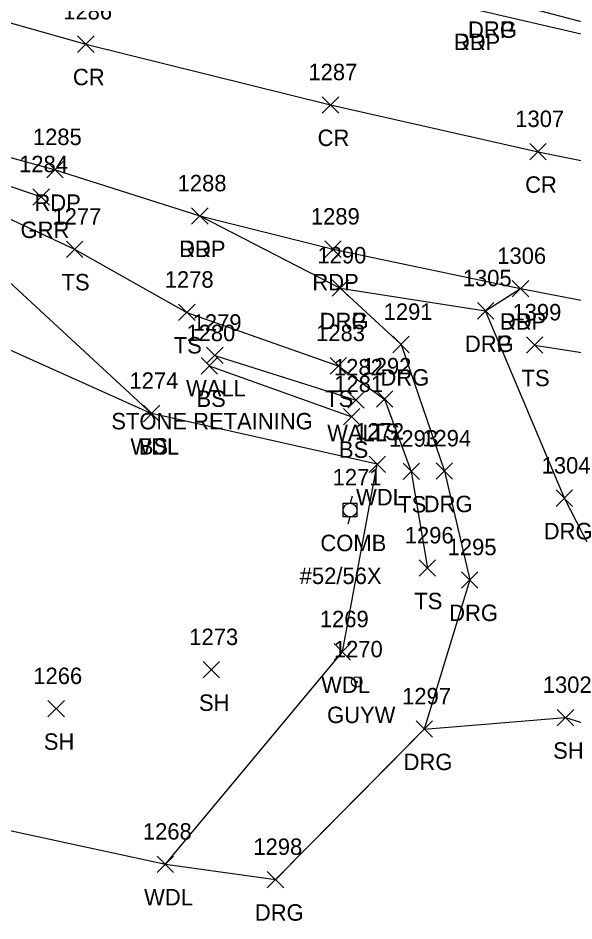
# Model space of a CAD drawing. Extents: x 1547013 to 1549434, y 267998 to 268739.
# Drawn here: x 1548599.8 to 1548667.4, y 267998.1 to 268107.9 of the extents above; entities that cross this region are included whole.
import ezdxf

# ---------------------------------------------------------------- set-up
doc = ezdxf.new("R2010")
doc.units = 0
for name, color, linetype in [('L_A', 7, 'Continuous'), ('L_C', 7, 'Continuous'), ('L_I', 7, 'Continuous'), ('L_TIC', 7, 'Continuous'), ('LAWA', 7, 'Continuous'), ('LELB', 7, 'Continuous'), ('LSOGP', 7, 'Continuous'), ('LW', 7, 'Continuous'), ('P_A', 7, 'Continuous'), ('P_I', 7, 'Continuous'), ('P_TIC', 7, 'Continuous'), ('PET', 7, 'Continuous'), ('PRC', 7, 'Continuous'), ('R_A', 7, 'Continuous'), ('R_I', 7, 'Continuous'), ('R_TIC', 7, 'Continuous'), ('RDG', 7, 'Continuous'), ('RDP', 7, 'Continuous'), ('RGR', 7, 'Continuous'), ('U_A', 7, 'Continuous'), ('U_C', 7, 'Continuous'), ('U_I', 7, 'Continuous'), ('UP', 7, 'Continuous'), ('UPGW', 7, 'Continuous')]:
    doc.layers.add(name, color=color, linetype=linetype)

msp = doc.modelspace()

# ---------------------------------------------------------------- linework, layer by layer
at = {"layer": 'L_TIC'}
for points in [[(1548605.66, 268078.82), (1548607.66, 268080.82)], [(1548607.66, 268078.82), (1548605.66, 268080.82)], [(1548619.32, 268071.15), (1548621.32, 268073.15)], [(1548621.32, 268071.15), (1548619.32, 268073.15)], [(1548661.66, 268067.17), (1548663.66, 268069.17)], [(1548663.66, 268067.17), (1548661.66, 268069.17)], [(1548622.73, 268065.92), (1548624.73, 268067.92)], [(1548624.73, 268065.92), (1548622.73, 268067.92)], [(1548622.05, 268064.65), (1548624.05, 268066.65)], [(1548624.05, 268064.65), (1548622.05, 268066.65)], [(1548637.75, 268064.65), (1548639.75, 268066.65)], [(1548639.75, 268064.65), (1548637.75, 268066.65)], [(1548643.4, 268060.61), (1548645.4, 268062.61)], [(1548645.4, 268060.61), (1548643.4, 268062.61)], [(1548639.92, 268060.48), (1548641.92, 268062.48)], [(1548641.92, 268060.48), (1548639.92, 268062.48)], [(1548615.03, 268058.85), (1548617.03, 268060.85)], [(1548617.03, 268058.85), (1548615.03, 268060.85)], [(1548615.03, 268058.85), (1548617.03, 268060.85)], [(1548617.03, 268058.85), (1548615.03, 268060.85)], [(1548639.4, 268058.46), (1548641.4, 268060.46)], [(1548641.4, 268058.46), (1548639.4, 268060.46)], [(1548642.5, 268052.68), (1548644.5, 268054.68)], [(1548644.5, 268052.68), (1548642.5, 268054.68)], [(1548646.64, 268051.81), (1548648.64, 268053.81)], [(1548648.64, 268051.81), (1548646.64, 268053.81)], [(1548648.6, 268040.05), (1548650.6, 268042.05)], [(1548650.6, 268040.05), (1548648.6, 268042.05)], [(1548638.26, 268029.86), (1548640.26, 268031.86)], [(1548640.26, 268029.86), (1548638.26, 268031.86)], [(1548622.31, 268027.69), (1548624.31, 268029.69)], [(1548624.31, 268027.69), (1548622.31, 268029.69)], [(1548603.42, 268022.95), (1548605.42, 268024.95)], [(1548605.42, 268022.95), (1548603.42, 268024.95)], [(1548665.42, 268021.87), (1548667.42, 268023.87)], [(1548667.42, 268021.87), (1548665.42, 268023.87)], [(1548616.71, 268004.03), (1548618.71, 268006.03)], [(1548618.71, 268004.03), (1548616.71, 268006.03)]]:
    msp.add_lwpolyline(points, dxfattribs=at)
at = {"layer": 'LAWA'}
msp.add_lwpolyline([(1548532.99, 268010.68), (1548542.3, 268026), (1548565.76, 268021.3), (1548592.57, 268010.46), (1548617.71, 268005.03), (1548639.26, 268030.86), (1548643.5, 268053.68), (1548616.03, 268059.85), (1548595.41, 268078.87)], dxfattribs=at)
at = {"layer": 'LELB'}
for points in [[(1548272.57, 268212.48), (1548289.14, 268210.26), (1548307.62, 268202.44), (1548323.1, 268196.35), (1548369.71, 268173.31), (1548388.46, 268161.7), (1548422.32, 268150.28), (1548459.33, 268134.33), (1548490.6, 268122.37), (1548528.34, 268109.13), (1548567.41, 268095.24), (1548592.2, 268086.56), (1548606.66, 268079.82), (1548620.32, 268072.15), (1548638.75, 268065.65), (1548644.4, 268061.61), (1548647.64, 268052.81), (1548649.6, 268041.05)], [(1548561.51, 268077.59), (1548574.57, 268080.17), (1548596.31, 268068.68), (1548616.03, 268059.85)], [(1548662.66, 268068.17), (1548718.89, 268059.45), (1548749.16, 268054.19), (1548786.26, 268048.98), (1548815.59, 268046.57), (1548864.84, 268043.79)], [(1548623.05, 268065.65), (1548640.4, 268059.46)]]:
    msp.add_lwpolyline(points, dxfattribs=at)
at = {"layer": 'LSOGP'}
msp.add_lwpolyline([(1548448.23, 268090.84), (1548475.05, 268075.85), (1548475.61, 268055.12), (1548494.63, 268042.02), (1548506.57, 268030.26), (1548514.3, 268026.68), (1548515.43, 268025.99), (1548520.54, 268019.12), (1548523.56, 268016.08), (1548532.99, 268010.68), (1548542.3, 268026), (1548565.76, 268021.3), (1548592.57, 268010.46), (1548617.71, 268005.03), (1548631.11, 268003.17), (1548635.64, 268007.75), (1548640.17, 268012.32), (1548644.7, 268016.9), (1548649.22, 268021.48), (1548666.42, 268022.87), (1548707.91, 268010.05)], dxfattribs=at)
at = {"layer": 'LW'}
msp.add_lwpolyline([(1548623.73, 268066.92), (1548640.92, 268061.48)], dxfattribs=at)
at = {"layer": 'P_TIC'}
for points in [[(1548607.02, 268103.77), (1548609.02, 268105.77)], [(1548609.02, 268103.77), (1548607.02, 268105.77)], [(1548636.81, 268096.38), (1548638.81, 268098.38)], [(1548638.81, 268096.38), (1548636.81, 268098.38)], [(1548662.07, 268090.69), (1548664.07, 268092.69)], [(1548664.07, 268090.69), (1548662.07, 268092.69)], [(1548603.28, 268088.49), (1548605.28, 268090.49)], [(1548605.28, 268088.49), (1548603.28, 268090.49)], [(1548620.9, 268082.87), (1548622.9, 268084.87)], [(1548622.9, 268082.87), (1548620.9, 268084.87)], [(1548637.12, 268078.83), (1548639.12, 268080.83)], [(1548639.12, 268078.83), (1548637.12, 268080.83)], [(1548659.94, 268074.04), (1548661.94, 268076.04)], [(1548661.94, 268074.04), (1548659.94, 268076.04)]]:
    msp.add_lwpolyline(points, dxfattribs=at)
at = {"layer": 'PET'}
for points in [[(1548291.29, 268251.79), (1548331.75, 268232.06), (1548365.57, 268215.99), (1548397.04, 268199.92), (1548430.53, 268185.01), (1548469.56, 268167.88), (1548505.57, 268153.53), (1548548.45, 268139.73), (1548572.84, 268130.65), (1548596.65, 268123.57), (1548616.57, 268118.19), (1548655.34, 268109.04), (1548680.93, 268103.12), (1548700.8, 268099.76), (1548753.55, 268092.31), (1548788.11, 268088.53), (1548842.08, 268084.26), (1548868.98, 268083.24)], [(1548277.31, 268222.58), (1548324.08, 268200.05), (1548370.89, 268177.56), (1548421.34, 268155.12), (1548457.66, 268139.55), (1548491.25, 268126.1), (1548528.96, 268112.02), (1548568.2, 268099.41), (1548604.28, 268089.49), (1548621.9, 268083.87), (1548638.12, 268079.83), (1548660.94, 268075.04), (1548683.04, 268070.81), (1548718.59, 268065.27), (1548750.02, 268060.75), (1548786.09, 268057.26), (1548818, 268054.36), (1548866.14, 268051.84)]]:
    msp.add_lwpolyline(points, dxfattribs=at)
at = {"layer": 'PRC'}
msp.add_lwpolyline([(1548285.23, 268237.15), (1548330.43, 268214.75), (1548376.37, 268192.58), (1548426.54, 268169.59), (1548464.29, 268153.5), (1548497.35, 268140.09), (1548534.69, 268126.49), (1548572.93, 268114.69), (1548608.02, 268104.77), (1548637.81, 268097.38), (1548663.07, 268091.69), (1548686.38, 268086.96), (1548723.69, 268081.05), (1548751.9, 268076.9), (1548786.74, 268073.36), (1548818.76, 268070.54), (1548866.8, 268068.08)], dxfattribs=at)
at = {"layer": 'R_TIC'}
for points in [[(1548601.59, 268085.19), (1548603.59, 268087.19)], [(1548603.59, 268085.19), (1548601.59, 268087.19)], [(1548620.9, 268082.87), (1548622.9, 268084.87)], [(1548622.9, 268082.87), (1548620.9, 268084.87)], [(1548638, 268074.1), (1548640, 268076.1)], [(1548640, 268074.1), (1548638, 268076.1)], [(1548638, 268074.1), (1548640, 268076.1)], [(1548640, 268074.1), (1548638, 268076.1)], [(1548659.94, 268074.04), (1548661.94, 268076.04)], [(1548661.94, 268074.04), (1548659.94, 268076.04)], [(1548655.69, 268071.33), (1548657.69, 268073.33)], [(1548657.69, 268071.33), (1548655.69, 268073.33)], [(1548655.69, 268071.33), (1548657.69, 268073.33)], [(1548657.69, 268071.33), (1548655.69, 268073.33)], [(1548645.4, 268067.24), (1548647.4, 268069.24)], [(1548647.4, 268067.24), (1548645.4, 268069.24)], [(1548650.67, 268051.85), (1548652.67, 268053.85)], [(1548652.67, 268051.85), (1548650.67, 268053.85)], [(1548665.28, 268048.55), (1548667.28, 268050.55)], [(1548667.28, 268048.55), (1548665.28, 268050.55)], [(1548653.76, 268038.61), (1548655.76, 268040.61)], [(1548655.76, 268038.61), (1548653.76, 268040.61)], [(1548648.22, 268020.48), (1548650.22, 268022.48)], [(1548650.22, 268020.48), (1548648.22, 268022.48)], [(1548630.11, 268002.17), (1548632.11, 268004.17)], [(1548632.11, 268002.17), (1548630.11, 268004.17)]]:
    msp.add_lwpolyline(points, dxfattribs=at)
at = {"layer": 'RDG'}
for points in [[(1548639, 268075.1), (1548646.4, 268068.24), (1548651.67, 268052.85), (1548654.76, 268039.61), (1548649.22, 268021.48), (1548631.11, 268003.17)], [(1548707.91, 268010.05), (1548708.41, 268019.21), (1548683.39, 268030.32), (1548671.71, 268039.07), (1548666.28, 268049.55), (1548656.69, 268072.33)]]:
    msp.add_lwpolyline(points, dxfattribs=at)
at = {"layer": 'RDP'}
for points in [[(1548655.34, 268109.04), (1548657.06, 268110.53), (1548678.17, 268104.93), (1548680.93, 268103.12)], [(1548621.9, 268083.87), (1548639, 268075.1), (1548656.69, 268072.33), (1548660.94, 268075.04)]]:
    msp.add_lwpolyline(points, dxfattribs=at)
at = {"layer": 'RGR'}
msp.add_lwpolyline([(1548388.8, 268165.09), (1548420.43, 268153.83), (1548460.75, 268137.25), (1548490.9, 268125.1), (1548529.02, 268110.81), (1548568.38, 268097.87), (1548602.59, 268086.19)], dxfattribs=at)
at = {"layer": 'UP'}
for p, q in [((1548640.45, 268049.78), (1548640.2, 268048.94)), ((1548639.36, 268047.28), (1548639.36, 268048.94)), ((1548639.36, 268048.94), (1548641.03, 268048.94)), ((1548641.03, 268048.94), (1548641.03, 268047.28)), ((1548641.03, 268047.28), (1548639.36, 268047.28)), ((1548639.95, 268046.44), (1548640.2, 268047.28)), ((1548640.2, 268048.11), (1548640.2, 268048.11))]:
    msp.add_line(p, q, dxfattribs=at)
msp.add_circle((1548640.2, 268048.11), 0.833, dxfattribs=at)
at = {"layer": 'UPGW'}
for radius in [0.625, 0.0833]:
    msp.add_circle((1548641, 268027.2), radius, dxfattribs=at)

# ---------------------------------------------------------------- texts
at = {"layer": 'L_A'}
for s, p in [('TS', (1548605.07, 268074.82)), ('TS', (1548618.73, 268067.15)), ('TS', (1548661.07, 268063.17)), ('WALL', (1548620.22, 268061.92)), ('BS', (1548621.49, 268060.65)), ('TS', (1548637.16, 268060.65)), ('WALL', (1548637.41, 268056.48)), ('TS', (1548642.81, 268056.61)), ('WDL', (1548613.45, 268054.85)), ('BS', (1548614.47, 268054.85)), ('BS', (1548638.84, 268054.46)), ('WDL', (1548640.92, 268048.68)), ('TS', (1548646.05, 268047.81)), ('TS', (1548648.01, 268036.05)), ('WDL', (1548636.68, 268025.86)), ('SH', (1548621.8, 268023.69)), ('SH', (1548602.91, 268018.95)), ('SH', (1548664.91, 268017.87)), ('WDL', (1548615.12, 268000.03))]:
    msp.add_text(s, height=2, dxfattribs=at).set_placement(p)
at = {"layer": 'L_C'}
msp.add_text('STONE RETAINING', height=2, dxfattribs=at).set_placement((1548611.13, 268057.92))
at = {"layer": 'L_I'}
for s, p in [('1277', (1548603.96, 268082.82)), ('1278', (1548617.63, 268075.15)), ('1399', (1548659.96, 268071.17)), ('1279', (1548621.03, 268069.92)), ('1280', (1548620.27, 268068.65)), ('1283', (1548636.06, 268068.65)), ('1282', (1548638.23, 268064.48)), ('1292', (1548641.71, 268064.61)), ('1274', (1548613.34, 268062.85)), ('1274', (1548613.34, 268062.85)), ('1281', (1548638.27, 268062.46)), ('1272', (1548640.81, 268056.68)), ('1293', (1548644.95, 268055.81)), ('1296', (1548646.85, 268044.05)), ('1269', (1548636.51, 268033.86)), ('1273', (1548620.62, 268031.69)), ('1266', (1548601.63, 268026.95)), ('1302', (1548663.65, 268025.87)), ('1268', (1548614.97, 268008.03))]:
    msp.add_text(s, height=2, dxfattribs=at).set_placement(p)
at = {"layer": 'P_A'}
for s, p in [('RDP', (1548652.83, 268104.04)), ('CR', (1548606.45, 268099.77)), ('CR', (1548636.24, 268092.38)), ('CR', (1548661.5, 268086.69)), ('RDP', (1548601.77, 268084.49)), ('RDP', (1548619.38, 268078.87)), ('RDP', (1548635.6, 268074.83)), ('RDP', (1548658.43, 268070.04))]:
    msp.add_text(s, height=2, dxfattribs=at).set_placement(p)
at = {"layer": 'P_I'}
for s, p in [('1286', (1548605.27, 268107.77)), ('1287', (1548635.12, 268100.38)), ('1307', (1548660.3, 268094.69)), ('1285', (1548601.58, 268092.49)), ('1288', (1548619.2, 268086.87)), ('1289', (1548635.42, 268082.83)), ('1306', (1548658.11, 268078.04))]:
    msp.add_text(s, height=2, dxfattribs=at).set_placement(p)
at = {"layer": 'R_A'}
for s, p in [('DRG', (1548654.55, 268105.53)), ('DRP', (1548654.55, 268105.53)), ('DRP', (1548652.83, 268104.04)), ('GRR', (1548600.08, 268081.19)), ('DRP', (1548619.38, 268078.87)), ('DRG', (1548636.49, 268070.1)), ('DRP', (1548636.49, 268070.1)), ('DRP', (1548658.43, 268070.04)), ('DRG', (1548654.17, 268067.33)), ('DRP', (1548654.17, 268067.33)), ('DRG', (1548643.89, 268063.24)), ('DRG', (1548649.16, 268047.85)), ('DRG', (1548663.77, 268044.55)), ('DRG', (1548652.25, 268034.61)), ('DRG', (1548646.71, 268016.48)), ('DRG', (1548628.6, 267998.17))]:
    msp.add_text(s, height=2, dxfattribs=at).set_placement(p)
at = {"layer": 'R_I'}
for s, p in [('1284', (1548599.9, 268089.19)), ('1288', (1548619.2, 268086.87)), ('1290', (1548636.22, 268078.1)), ('1290', (1548636.22, 268078.1)), ('1306', (1548658.11, 268078.04)), ('1305', (1548653.91, 268075.33)), ('1305', (1548653.91, 268075.33)), ('1291', (1548644.28, 268071.24)), ('1294', (1548648.98, 268055.85)), ('1304', (1548663.51, 268052.55)), ('1295', (1548652.07, 268042.61)), ('1297', (1548646.53, 268024.48)), ('1298', (1548628.42, 268006.17))]:
    msp.add_text(s, height=2, dxfattribs=at).set_placement(p)
at = {"layer": 'U_A'}
for s, p in [('COMB', (1548636.58, 268043.11)), ('GUYW', (1548637.39, 268022.2))]:
    msp.add_text(s, height=2, dxfattribs=at).set_placement(p)
at = {"layer": 'U_C'}
msp.add_text('#52/56X', height=2, dxfattribs=at).set_placement((1548634.06, 268039.11))
at = {"layer": 'U_I'}
for s, p in [('1271', (1548638.07, 268051.11)), ('1270', (1548638.22, 268030.2))]:
    msp.add_text(s, height=2, dxfattribs=at).set_placement(p)

doc.saveas('drawing.dxf')
